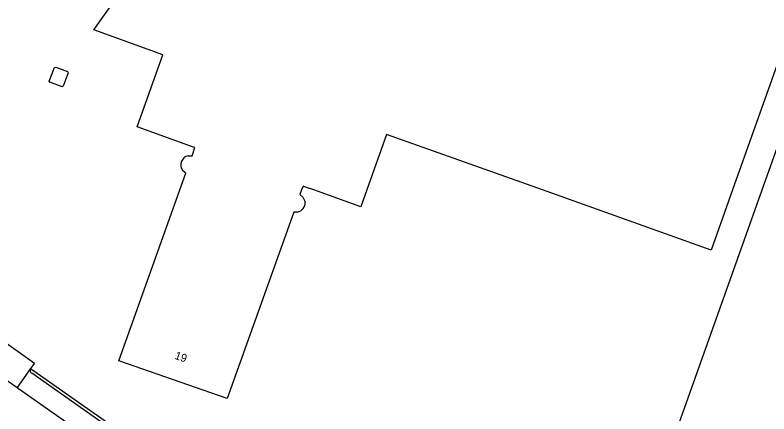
# Model space of a CAD drawing. Extents: x 155018 to 156648, y 383980 to 385733.
# Drawn here: x 155513.9 to 155608.1, y 384972 to 385021.9 of the extents above; entities that cross this region are included whole.
import ezdxf

# ---------------------------------------------------------------- set-up
doc = ezdxf.new("R2010")
doc.units = 0
for name, color, linetype in [('IMGEO_Pand', 7, 'Continuous'), ('IMGEO_Pand_nummerreeks', 7, 'Continuous'), ('IMGEO_Rijbaan_lokaal_gesloten', 7, 'Continuous'), ('IMGEO_Voetpad_open', 7, 'Continuous')]:
    doc.layers.add(name, color=color, linetype=linetype)

msp = doc.modelspace()

# ---------------------------------------------------------------- linework, layer by layer
at = {"layer": 'IMGEO_Pand'}
for points in [[(155535.473, 385004.273), (155535.985, 385004.271), (155536.336, 385005.323), (155535.896, 385005.456), (155529.096, 385007.886), (155532.322, 385016.918), (155523.708, 385020.015), (155526.582, 385024.107), (155553.008, 385061.731), (155555.772, 385060.745), (155568.458, 385096.335), (155630.019, 385074.396), (155603.521, 385000)], [(155630.178, 384929.273), (155625.14, 384931.07), (155632.162, 384950.755), (155623.212, 384953.942), (155618.1, 384939.84), (155589.46, 384950.07), (155591.136, 384954.781), (155607.234, 385000), (155633.333, 385073.311), (155662.065, 385063.078), (155658.666, 385053.535), (155667.974, 385050.22)], [(155519.719, 385012.905), (155518.205, 385013.48), (155518.128, 385013.619), (155518.771, 385015.316), (155518.938, 385015.371), (155520.419, 385014.813), (155520.474, 385014.663), (155519.862, 385012.978), (155519.719, 385012.905)], [(155603.521, 385000), (155602.521, 384997.193), (155600.843, 384992.482), (155579.769, 385000), (155560.285, 385006.951), (155557.797, 385000), (155557.05, 384997.913), (155551.193, 385000), (155550.264, 385000.331), (155549.839, 385000.497), (155549.65, 385000), (155549.437, 384999.439), (155549.832, 384999.123), (155550.085, 384998.504)], [(155549.161, 384997.245), (155548.687, 384997.244), (155540.351, 384973.929), (155526.816, 384978.65), (155534.46, 385000), (155535.208, 385002.089), (155534.809, 385002.413)]]:
    msp.add_lwpolyline(points, dxfattribs=at)
for centre, radius, start, end in [((155535.726, 385003.134), 1.166, 102.51087, 218.19709), ((155548.923, 384998.389), 1.168, 281.77899, 5.66994)]:
    msp.add_arc(centre, radius, start, end, dxfattribs=at)
at = {"layer": 'IMGEO_Rijbaan_lokaal_gesloten'}
for points in [[(155509.167, 384978.777), (155514.115, 384975.3)], [(155514.115, 384975.3), (155514.295, 384975.174), (155551.965, 384948.699)]]:
    msp.add_lwpolyline(points, dxfattribs=at)
at = {"layer": 'IMGEO_Voetpad_open'}
for points in [[(155510.83, 384981.203), (155511.294, 384981.88), (155516.258, 384978.35), (155515.775, 384977.663)], [(155515.775, 384977.663), (155514.115, 384975.3)], [(155515.775, 384977.663), (155553.601, 384951.142)], [(155552.875, 384951.036), (155515.938, 384977.083)]]:
    msp.add_lwpolyline(points, dxfattribs=at)
msp.add_arc((155516.12, 384977.447), 0.407, 147.91031, 243.48408, dxfattribs=at)

# ---------------------------------------------------------------- texts
at = {"layer": 'IMGEO_Pand_nummerreeks'}
msp.add_text('19', height=1, rotation=340.77126, dxfattribs=at).set_placement((155533.72, 384978.911))

doc.saveas('drawing.dxf')
